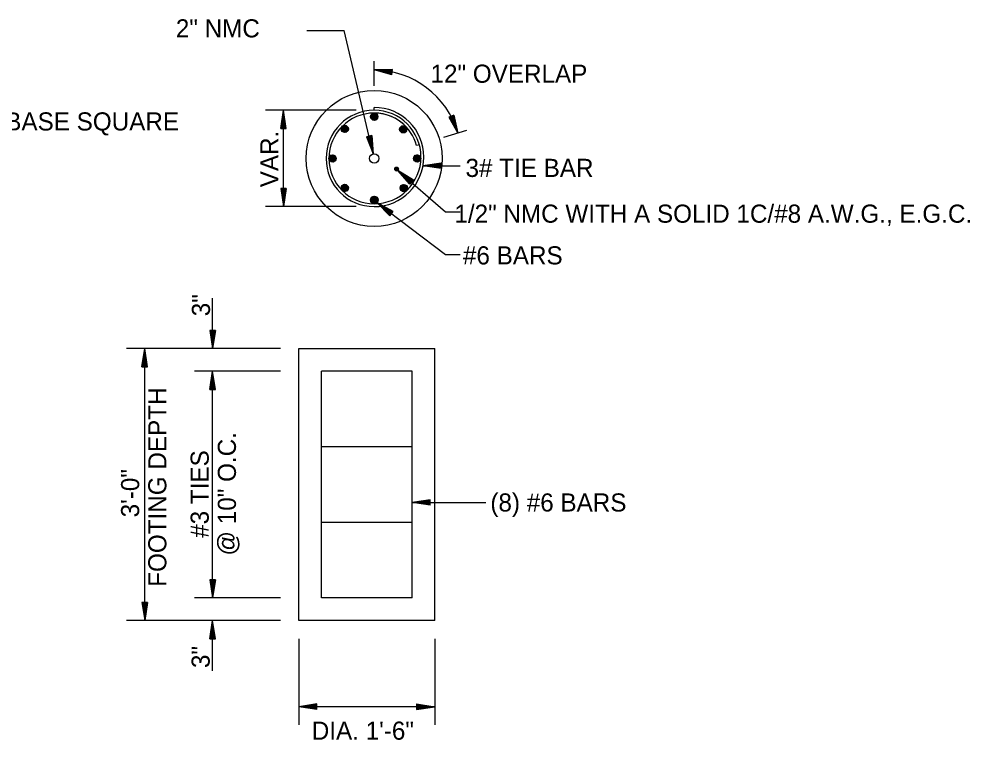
# Model space of a CAD drawing. Extents: x 418532 to 420296, y -565948 to -565286.
# Drawn here: x 419394.2 to 419630.3, y -565491.4 to -565312.5 of the extents above; entities that cross this region are included whole.
import ezdxf

# ---------------------------------------------------------------- set-up
doc = ezdxf.new("R2010")
doc.units = 0
doc.layers.add('R_Draft', color=7, linetype='Continuous')

msp = doc.modelspace()

# ---------------------------------------------------------------- linework, layer by layer
at = {"layer": 'R_Draft'}
for p, q in [((419465.68, -565315.3), (419474.89, -565315.3)), ((419482.12, -565345.92), (419474.89, -565315.3)), ((419482.39, -565329.06), (419482.39, -565322.9)), ((419486.94, -565324.96), (419482.39, -565325.05)), ((419486.77, -565326.29), (419482.39, -565325.05)), ((419486.93, -565325.07), (419483.14, -565325.15)), ((419486.78, -565326.18), (419483.14, -565325.15)), ((419486.91, -565325.18), (419483.9, -565325.25)), ((419486.8, -565326.07), (419483.9, -565325.25)), ((419486.9, -565325.29), (419484.65, -565325.34)), ((419486.81, -565325.96), (419484.65, -565325.34)), ((419486.88, -565325.41), (419485.4, -565325.44)), ((419486.83, -565325.84), (419485.4, -565325.44)), ((419486.87, -565325.52), (419486.15, -565325.53)), ((419486.84, -565325.73), (419486.15, -565325.53)), ((419486.77, -565326.29), (419486.94, -565324.96)), ((419477.89, -565335.1), (419455.39, -565335.1)), ((419459.21, -565339.6), (419459.89, -565335.1)), ((419459.32, -565339.6), (419459.89, -565335.86)), ((419459.89, -565359.01), (419459.89, -565335.1)), ((419460.56, -565339.6), (419459.89, -565335.1)), ((419460.45, -565339.6), (419459.89, -565335.86)), ((419481.49, -565336.75), (419482.43, -565335.81)), ((419481.49, -565336.58), (419482.26, -565335.82)), ((419481.5, -565336.89), (419482.57, -565335.83)), ((419481.54, -565337.01), (419482.69, -565335.86)), ((419482.39, -565335.1), (419482.39, -565334.4)), ((419459.44, -565339.6), (419459.89, -565336.63)), ((419459.55, -565339.6), (419459.89, -565337.38)), ((419459.67, -565339.6), (419459.89, -565338.14)), ((419460.33, -565339.6), (419459.89, -565336.63)), ((419460.22, -565339.6), (419459.89, -565337.38)), ((419460.11, -565339.6), (419459.89, -565338.14)), ((419481.55, -565336.36), (419482.04, -565335.88)), ((419481.59, -565337.13), (419482.8, -565335.91)), ((419481.65, -565337.22), (419482.9, -565335.97)), ((419481.72, -565337.31), (419482.99, -565336.04)), ((419481.8, -565337.39), (419483.07, -565336.12)), ((419481.89, -565337.46), (419483.14, -565336.21)), ((419481.99, -565337.52), (419483.19, -565336.31)), ((419482.1, -565337.56), (419483.24, -565336.43)), ((419482.23, -565337.6), (419483.27, -565336.55)), ((419482.38, -565337.61), (419483.29, -565336.7)), ((419482.55, -565337.59), (419483.27, -565336.87)), ((419482.79, -565337.51), (419483.19, -565337.12)), ((419502.14, -565336.36), (419500.88, -565336.84)), ((419500.88, -565336.84), (419503.12, -565340.8)), ((419500.98, -565336.8), (419502.85, -565340.1)), ((419501.09, -565336.76), (419502.57, -565339.38)), ((419501.2, -565336.72), (419502.31, -565338.68)), ((419501.3, -565336.68), (419502.03, -565337.97)), ((419501.41, -565336.64), (419501.76, -565337.26)), ((419501.61, -565336.56), (419501.76, -565337.26)), ((419501.71, -565336.52), (419502.03, -565337.97)), ((419501.82, -565336.48), (419502.31, -565338.68)), ((419501.93, -565336.44), (419502.57, -565339.38)), ((419502.03, -565336.4), (419502.85, -565340.1)), ((419502.14, -565336.36), (419503.12, -565340.8)), ((419459.21, -565339.6), (419460.56, -565339.6)), ((419459.78, -565339.6), (419459.89, -565338.89)), ((419459.99, -565339.6), (419459.89, -565338.89)), ((419474.17, -565339.7), (419475.03, -565338.84)), ((419474.17, -565339.85), (419475.18, -565338.85)), ((419474.2, -565339.99), (419475.31, -565338.87)), ((419474.2, -565339.51), (419474.84, -565338.87)), ((419474.24, -565340.1), (419475.43, -565338.92)), ((419474.3, -565340.21), (419475.53, -565338.97)), ((419474.34, -565339.21), (419474.54, -565339.01)), ((419474.36, -565340.3), (419475.63, -565339.04)), ((419474.44, -565340.38), (419475.71, -565339.11)), ((419474.52, -565340.46), (419475.79, -565339.2)), ((419474.62, -565340.52), (419475.85, -565339.29)), ((419474.73, -565340.57), (419475.9, -565339.4)), ((419474.85, -565340.61), (419475.94, -565339.52)), ((419474.98, -565340.64), (419475.96, -565339.66)), ((419475.14, -565340.64), (419475.96, -565339.81)), ((419475.34, -565340.6), (419475.92, -565340.01)), ((419488.71, -565339.92), (419489.68, -565338.95)), ((419488.71, -565339.77), (419489.53, -565338.95)), ((419488.73, -565340.06), (419489.82, -565338.97)), ((419488.75, -565339.57), (419489.33, -565338.99)), ((419488.77, -565340.18), (419489.94, -565339.01)), ((419488.82, -565340.29), (419490.05, -565339.06)), ((419488.88, -565340.38), (419490.14, -565339.12)), ((419488.96, -565340.47), (419490.23, -565339.2)), ((419489.04, -565340.54), (419490.31, -565339.28)), ((419489.13, -565340.61), (419490.37, -565339.37)), ((419489.24, -565340.66), (419490.43, -565339.48)), ((419489.36, -565340.71), (419490.47, -565339.59)), ((419489.49, -565340.73), (419490.5, -565339.73)), ((419489.64, -565340.74), (419490.5, -565339.88)), ((419489.83, -565340.71), (419490.47, -565340.06)), ((419490.12, -565340.58), (419490.34, -565340.36)), ((419505.27, -565340.15), (419499.62, -565341.86)), ((419481.77, -565341.38), (419480.45, -565341.68)), ((419480.45, -565341.68), (419482.12, -565345.92)), ((419480.56, -565341.66), (419481.95, -565345.19)), ((419480.68, -565341.63), (419481.78, -565344.43)), ((419480.79, -565341.61), (419481.61, -565343.7)), ((419480.9, -565341.58), (419481.44, -565342.96)), ((419481.01, -565341.56), (419481.27, -565342.22)), ((419481.22, -565341.51), (419481.27, -565342.22)), ((419481.33, -565341.48), (419481.44, -565342.96)), ((419481.44, -565341.46), (419481.61, -565343.7)), ((419481.55, -565341.43), (419481.78, -565344.43)), ((419481.66, -565341.41), (419481.95, -565345.19)), ((419481.77, -565341.38), (419482.12, -565345.92)), ((419493.59, -565343.68), (419492.91, -565343.88)), ((419471.14, -565347.01), (419471.99, -565346.16)), ((419471.14, -565347.17), (419472.15, -565346.17)), ((419471.17, -565347.3), (419472.28, -565346.19)), ((419471.17, -565346.83), (419471.8, -565346.19)), ((419471.21, -565347.42), (419472.4, -565346.23)), ((419471.26, -565347.52), (419472.5, -565346.29)), ((419471.32, -565346.51), (419471.49, -565346.34)), ((419471.33, -565347.62), (419472.59, -565346.35)), ((419471.41, -565347.7), (419472.68, -565346.43)), ((419471.49, -565347.77), (419472.75, -565346.51)), ((419471.59, -565347.84), (419472.82, -565346.61)), ((419471.69, -565347.89), (419472.87, -565346.72)), ((419471.81, -565347.93), (419472.91, -565346.83)), ((419471.95, -565347.95), (419472.93, -565346.97)), ((419472.1, -565347.96), (419472.93, -565347.13)), ((419472.3, -565347.92), (419472.9, -565347.32)), ((419492.15, -565347.05), (419493.03, -565346.16)), ((419492.16, -565347.2), (419493.18, -565346.17)), ((419492.17, -565346.87), (419492.85, -565346.18)), ((419492.19, -565347.33), (419493.31, -565346.2)), ((419492.23, -565347.44), (419493.43, -565346.24)), ((419492.27, -565346.61), (419492.59, -565346.28)), ((419492.29, -565347.54), (419493.53, -565346.3)), ((419492.35, -565347.63), (419493.62, -565346.37)), ((419492.43, -565347.72), (419493.7, -565346.44)), ((419492.52, -565347.79), (419493.77, -565346.53)), ((419492.62, -565347.85), (419493.84, -565346.63)), ((419492.72, -565347.9), (419493.89, -565346.74)), ((419492.85, -565347.94), (419493.92, -565346.86)), ((419492.99, -565347.96), (419493.94, -565347)), ((419493.15, -565347.95), (419493.94, -565347.16)), ((419493.36, -565347.9), (419493.89, -565347.37)), ((419487.46, -565349.68), (419487.93, -565349.22)), ((419487.48, -565349.82), (419488.07, -565349.23)), ((419487.51, -565349.47), (419487.71, -565349.27)), ((419487.53, -565349.93), (419488.18, -565349.28)), ((419487.6, -565350.02), (419488.26, -565349.35)), ((419487.69, -565350.09), (419488.33, -565349.44)), ((419487.8, -565350.13), (419488.38, -565349.56)), ((419487.94, -565350.15), (419488.4, -565349.7)), ((419488.17, -565350.09), (419488.34, -565349.92)), ((419488.26, -565350.02), (419500.1, -565360.35)), ((419491.23, -565353.48), (419488.26, -565350.02)), ((419492.11, -565352.45), (419488.26, -565350.02)), ((419498.99, -565348.23), (419494.49, -565348.91)), ((419494.49, -565348.91), (419503.7, -565348.91)), ((419498.99, -565349.58), (419494.49, -565348.91)), ((419498.99, -565348.35), (419495.25, -565348.91)), ((419498.99, -565349.47), (419495.25, -565348.91)), ((419498.99, -565348.46), (419496.02, -565348.91)), ((419498.99, -565349.36), (419496.02, -565348.91)), ((419498.99, -565348.57), (419496.77, -565348.91)), ((419498.99, -565349.24), (419496.77, -565348.91)), ((419498.99, -565348.69), (419497.53, -565348.91)), ((419498.99, -565349.13), (419497.53, -565348.91)), ((419498.99, -565348.8), (419498.28, -565348.91)), ((419498.99, -565349.01), (419498.28, -565348.91)), ((419498.99, -565349.58), (419498.99, -565348.23)), ((419491.3, -565353.39), (419488.83, -565350.52)), ((419492.04, -565352.54), (419488.83, -565350.52)), ((419491.96, -565352.63), (419489.42, -565351.02)), ((419491.38, -565353.3), (419489.42, -565351.02)), ((419491.45, -565353.22), (419489.98, -565351.51)), ((419491.89, -565352.71), (419489.98, -565351.51)), ((419491.81, -565352.8), (419490.56, -565352.01)), ((419491.53, -565353.13), (419490.56, -565352.01)), ((419459.21, -565354.51), (419459.89, -565359.01)), ((419460.56, -565354.51), (419459.21, -565354.51)), ((419459.32, -565354.51), (419459.89, -565358.26)), ((419459.44, -565354.51), (419459.89, -565357.49)), ((419459.55, -565354.51), (419459.89, -565356.74)), ((419459.67, -565354.51), (419459.89, -565355.98)), ((419459.78, -565354.51), (419459.89, -565355.22)), ((419460.56, -565354.51), (419459.89, -565359.01)), ((419460.1, -565354.51), (419459.89, -565355.98)), ((419460.33, -565354.51), (419459.89, -565357.49)), ((419460.45, -565354.51), (419459.89, -565358.26)), ((419460.22, -565354.51), (419459.89, -565356.74)), ((419459.99, -565354.51), (419459.89, -565355.22)), ((419474.17, -565354.46), (419475.15, -565353.48)), ((419474.17, -565354.3), (419474.99, -565353.48)), ((419474.19, -565354.6), (419475.29, -565353.5)), ((419474.21, -565354.1), (419474.79, -565353.52)), ((419474.23, -565354.72), (419475.41, -565353.54)), ((419474.29, -565354.82), (419475.51, -565353.6)), ((419474.35, -565354.92), (419475.61, -565353.66)), ((419474.42, -565355.01), (419475.69, -565353.73)), ((419474.51, -565355.08), (419475.77, -565353.82)), ((419474.6, -565355.15), (419475.84, -565353.91)), ((419474.7, -565355.2), (419475.89, -565354.01)), ((419474.82, -565355.24), (419475.93, -565354.13)), ((419474.95, -565355.27), (419475.96, -565354.26)), ((419475.11, -565355.28), (419475.97, -565354.42)), ((419475.29, -565355.25), (419475.94, -565354.6)), ((419488.85, -565354.38), (419489.71, -565353.52)), ((419488.86, -565354.53), (419489.86, -565353.53)), ((419488.88, -565354.19), (419489.52, -565353.55)), ((419488.88, -565354.66), (419489.99, -565353.56)), ((419488.92, -565354.78), (419490.11, -565353.6)), ((419488.98, -565354.89), (419490.21, -565353.65)), ((419489.03, -565353.88), (419489.21, -565353.7)), ((419489.04, -565354.98), (419490.31, -565353.72)), ((419489.12, -565355.06), (419490.39, -565353.79)), ((419489.2, -565355.14), (419490.47, -565353.88)), ((419489.3, -565355.2), (419490.53, -565353.97)), ((419489.41, -565355.25), (419490.58, -565354.08)), ((419489.53, -565355.29), (419490.62, -565354.2)), ((419489.66, -565355.32), (419490.64, -565354.33)), ((419489.82, -565355.32), (419490.65, -565354.49)), ((419490.02, -565355.28), (419490.61, -565354.69)), ((419491.74, -565352.89), (419491.13, -565352.5)), ((419491.6, -565353.05), (419491.13, -565352.5)), ((419491.23, -565353.48), (419492.11, -565352.45)), ((419475.59, -565355.11), (419475.8, -565354.9)), ((419481.45, -565357.46), (419482.47, -565356.44)), ((419481.45, -565357.3), (419482.31, -565356.44)), ((419481.48, -565357.59), (419482.61, -565356.46)), ((419481.49, -565357.1), (419482.12, -565356.47)), ((419481.51, -565357.71), (419482.73, -565356.5)), ((419481.56, -565357.82), (419482.84, -565356.55)), ((419481.63, -565357.92), (419482.93, -565356.61)), ((419481.69, -565356.74), (419481.75, -565356.68)), ((419481.7, -565358.01), (419483.02, -565356.68)), ((419481.78, -565358.09), (419483.1, -565356.76)), ((419481.87, -565358.15), (419483.17, -565356.86)), ((419481.97, -565358.21), (419483.23, -565356.96)), ((419482.08, -565358.26), (419483.27, -565357.07)), ((419477.89, -565359.01), (419455.39, -565359.01)), ((419482.21, -565358.29), (419483.31, -565357.19)), ((419482.35, -565358.31), (419483.32, -565357.34)), ((419482.52, -565358.3), (419483.31, -565357.51)), ((419482.74, -565358.24), (419483.25, -565357.72)), ((419483.06, -565358.03), (419500.1, -565370.91)), ((419486.25, -565361.27), (419483.06, -565358.03)), ((419487.06, -565360.2), (419483.06, -565358.03)), ((419486.31, -565361.18), (419483.66, -565358.48)), ((419486.99, -565360.29), (419483.66, -565358.48)), ((419486.92, -565360.38), (419484.28, -565358.95)), ((419486.38, -565361.09), (419484.28, -565358.95)), ((419486.45, -565361), (419484.88, -565359.4)), ((419486.85, -565360.47), (419484.88, -565359.4)), ((419486.79, -565360.56), (419485.48, -565359.86)), ((419486.52, -565360.91), (419485.48, -565359.86)), ((419486.72, -565360.65), (419486.08, -565360.31)), ((419486.59, -565360.82), (419486.08, -565360.31)), ((419486.25, -565361.27), (419487.06, -565360.2)), ((419500.1, -565360.35), (419503.7, -565360.35)), ((419500.1, -565370.91), (419503.7, -565370.91)), ((419442.28, -565394.26), (419442.28, -565381.75)), ((419441.61, -565389.76), (419442.28, -565394.26)), ((419442.96, -565389.76), (419441.61, -565389.76)), ((419441.72, -565389.76), (419442.28, -565393.51)), ((419441.84, -565389.76), (419442.28, -565392.73)), ((419441.95, -565389.76), (419442.28, -565391.99)), ((419442.06, -565389.76), (419442.28, -565391.22)), ((419442.18, -565389.76), (419442.28, -565390.47)), ((419442.96, -565389.76), (419442.28, -565394.26)), ((419442.5, -565389.76), (419442.28, -565391.22)), ((419442.73, -565389.76), (419442.28, -565392.73)), ((419442.85, -565389.76), (419442.28, -565393.51)), ((419442.62, -565389.76), (419442.28, -565391.99)), ((419442.39, -565389.76), (419442.28, -565390.47)), ((419459.16, -565394.26), (419420.91, -565394.26)), ((419424.73, -565398.76), (419425.41, -565394.26)), ((419425.41, -565461.76), (419425.41, -565394.26)), ((419426.08, -565398.76), (419425.41, -565394.26)), ((419463.66, -565461.76), (419463.66, -565394.26)), ((419463.66, -565394.26), (419497.41, -565394.26)), ((419497.41, -565461.76), (419497.41, -565394.26)), ((419424.85, -565398.76), (419425.41, -565395.01)), ((419424.96, -565398.76), (419425.41, -565395.79)), ((419425.07, -565398.76), (419425.41, -565396.53)), ((419425.97, -565398.76), (419425.41, -565395.01)), ((419425.86, -565398.76), (419425.41, -565395.79)), ((419425.74, -565398.76), (419425.41, -565396.53)), ((419424.73, -565398.76), (419426.08, -565398.76)), ((419425.19, -565398.76), (419425.41, -565397.3)), ((419425.3, -565398.76), (419425.41, -565398.05)), ((419425.63, -565398.76), (419425.41, -565397.3)), ((419425.52, -565398.76), (419425.41, -565398.05)), ((419459.16, -565399.88), (419437.78, -565399.88)), ((419441.61, -565404.38), (419442.28, -565399.88)), ((419441.72, -565404.38), (419442.28, -565400.64)), ((419441.84, -565404.38), (419442.28, -565401.41)), ((419442.28, -565456.13), (419442.28, -565399.88)), ((419442.96, -565404.38), (419442.28, -565399.88)), ((419442.85, -565404.38), (419442.28, -565400.64)), ((419442.73, -565404.38), (419442.28, -565401.41)), ((419491.78, -565399.88), (419469.28, -565399.88)), ((419469.28, -565456.13), (419469.28, -565399.88)), ((419491.78, -565456.13), (419491.78, -565399.88)), ((419441.95, -565404.38), (419442.28, -565402.16)), ((419442.07, -565404.38), (419442.28, -565402.92)), ((419442.18, -565404.38), (419442.28, -565403.67)), ((419442.62, -565404.38), (419442.28, -565402.16)), ((419442.5, -565404.38), (419442.28, -565402.92)), ((419442.39, -565404.38), (419442.28, -565403.67)), ((419441.61, -565404.38), (419442.96, -565404.38)), ((419491.78, -565418.63), (419469.28, -565418.63)), ((419496.29, -565431.78), (419491.79, -565432.45)), ((419496.29, -565433.13), (419491.79, -565432.45)), ((419491.79, -565432.45), (419510.12, -565432.45)), ((419496.29, -565431.89), (419492.55, -565432.45)), ((419496.29, -565433.01), (419492.55, -565432.45)), ((419496.29, -565432), (419493.32, -565432.45)), ((419496.29, -565432.9), (419493.32, -565432.45)), ((419496.29, -565432.12), (419494.07, -565432.45)), ((419496.29, -565432.79), (419494.07, -565432.45)), ((419496.29, -565432.23), (419494.83, -565432.45)), ((419496.29, -565432.67), (419494.83, -565432.45)), ((419496.29, -565432.35), (419495.58, -565432.45)), ((419496.29, -565432.56), (419495.58, -565432.45)), ((419496.29, -565433.13), (419496.29, -565431.78)), ((419491.78, -565437.38), (419469.28, -565437.38)), ((419441.61, -565451.63), (419442.28, -565456.13)), ((419442.96, -565451.63), (419441.61, -565451.63)), ((419441.72, -565451.63), (419442.28, -565455.38)), ((419441.84, -565451.63), (419442.28, -565454.61)), ((419441.95, -565451.63), (419442.28, -565453.86)), ((419442.06, -565451.63), (419442.28, -565453.1)), ((419442.18, -565451.63), (419442.28, -565452.35)), ((419442.96, -565451.63), (419442.28, -565456.13)), ((419442.5, -565451.63), (419442.28, -565453.1)), ((419442.73, -565451.63), (419442.28, -565454.61)), ((419442.85, -565451.63), (419442.28, -565455.38)), ((419442.62, -565451.63), (419442.28, -565453.86)), ((419442.39, -565451.63), (419442.28, -565452.35)), ((419459.16, -565456.13), (419437.78, -565456.13)), ((419491.78, -565456.13), (419469.28, -565456.13)), ((419424.73, -565457.26), (419425.41, -565461.76)), ((419426.08, -565457.26), (419424.73, -565457.26)), ((419424.85, -565457.26), (419425.41, -565461.01)), ((419424.96, -565457.26), (419425.41, -565460.23)), ((419425.07, -565457.26), (419425.41, -565459.49)), ((419425.19, -565457.26), (419425.41, -565458.72)), ((419425.3, -565457.26), (419425.41, -565457.97)), ((419426.08, -565457.26), (419425.41, -565461.76)), ((419425.63, -565457.26), (419425.41, -565458.72)), ((419425.86, -565457.26), (419425.41, -565460.23)), ((419425.97, -565457.26), (419425.41, -565461.01)), ((419425.74, -565457.26), (419425.41, -565459.49)), ((419425.52, -565457.26), (419425.41, -565457.97)), ((419459.16, -565461.76), (419420.91, -565461.76)), ((419441.61, -565466.26), (419442.28, -565461.76)), ((419441.72, -565466.26), (419442.28, -565462.51)), ((419441.84, -565466.26), (419442.28, -565463.29)), ((419442.28, -565474.27), (419442.28, -565461.76)), ((419442.96, -565466.26), (419442.28, -565461.76)), ((419442.85, -565466.26), (419442.28, -565462.51)), ((419442.73, -565466.26), (419442.28, -565463.29)), ((419497.41, -565461.76), (419463.66, -565461.76)), ((419441.95, -565466.26), (419442.28, -565464.03)), ((419442.07, -565466.26), (419442.28, -565464.8)), ((419442.18, -565466.26), (419442.28, -565465.55)), ((419442.62, -565466.26), (419442.28, -565464.03)), ((419442.5, -565466.26), (419442.28, -565464.8)), ((419442.39, -565466.26), (419442.28, -565465.55)), ((419441.61, -565466.26), (419442.96, -565466.26)), ((419463.66, -565466.26), (419463.66, -565487.63)), ((419497.41, -565466.26), (419497.41, -565487.63)), ((419468.16, -565482.46), (419463.66, -565483.13)), ((419497.41, -565483.13), (419463.66, -565483.13)), ((419468.16, -565483.81), (419463.66, -565483.13)), ((419468.16, -565482.57), (419464.41, -565483.13)), ((419468.16, -565483.7), (419464.41, -565483.13)), ((419468.16, -565482.69), (419465.18, -565483.13)), ((419468.16, -565483.58), (419465.18, -565483.13)), ((419468.16, -565482.8), (419465.93, -565483.13)), ((419468.16, -565483.47), (419465.93, -565483.13)), ((419468.16, -565482.91), (419466.7, -565483.13)), ((419468.16, -565483.35), (419466.7, -565483.13)), ((419468.16, -565483.03), (419467.45, -565483.13)), ((419468.16, -565483.24), (419467.45, -565483.13)), ((419468.16, -565483.81), (419468.16, -565482.46)), ((419492.91, -565482.46), (419497.41, -565483.13)), ((419492.91, -565482.46), (419492.91, -565483.81)), ((419492.91, -565482.57), (419496.66, -565483.13)), ((419492.91, -565482.69), (419495.88, -565483.13)), ((419492.91, -565482.8), (419495.13, -565483.13)), ((419492.91, -565482.92), (419494.37, -565483.13)), ((419492.91, -565483.03), (419493.62, -565483.13)), ((419492.91, -565483.81), (419497.41, -565483.13)), ((419492.91, -565483.36), (419494.37, -565483.13)), ((419492.91, -565483.58), (419495.88, -565483.13)), ((419492.91, -565483.7), (419496.66, -565483.13)), ((419492.91, -565483.47), (419495.13, -565483.13)), ((419492.91, -565483.24), (419493.62, -565483.13))]:
    msp.add_line(p, q, dxfattribs=at)
for centre, radius in [((419482.39, -565347.06), 16.87), ((419482.39, -565336.71), 0.9), ((419475.07, -565339.74), 0.9), ((419489.6, -565339.84), 0.9), ((419472.04, -565347.06), 0.9), ((419482.39, -565347.06), 1.17), ((419493.05, -565347.06), 0.9), ((419487.93, -565349.68), 0.469), ((419475.07, -565354.38), 0.9), ((419489.75, -565354.42), 0.9), ((419482.39, -565357.37), 0.937)]:
    msp.add_circle(centre, radius, dxfattribs=at)
for centre, radius, start, end in [((419482.39, -565346.71), 21.56, 15.8939, 90), ((419482.39, -565347.06), 11.95, 90, 270), ((419482.39, -565347.06), 11.25, 90, 270), ((419482.39, -565346.71), 12.31, 270, 90), ((419482.39, -565346.71), 11.6, 270, 90), ((419482.39, -565346.71), 10.9, 43.6894, 90), ((419482.39, -565346.71), 10.9, 15.0162, 90)]:
    msp.add_arc(centre, radius, start, end, dxfattribs=at)

# ---------------------------------------------------------------- texts
for s, p in [('2" NMC', (419433.14, -565317.03)), ('12" OVERLAP', (419496.36, -565328.28)), ('ANCHOR BASE SQUARE', (419363.05, -565340.13)), ('3# TIE BAR', (419505.05, -565351.66)), (' 1/2" NMC WITH A SOLID 1C/#8 A.W.G., E.G.C.', (419500.62, -565363.02)), ('#6 BARS', (419504.41, -565373.37)), ('(8) #6 BARS', (419511.22, -565434.7)), ('DIA. 1\'-6"', (419466.89, -565491.33))]:
    msp.add_text(s, height=4.5, dxfattribs=at).set_placement(p)
for s, p in [('VAR.', (419458.61, -565354.22)), ('3"', (419441.62, -565386.23)), ('FOOTING DEPTH', (419430.79, -565453.38)), ('@ 10" O.C.', (419448.06, -565445.63)), ('#3 TIES', (419441.31, -565441.23)), ('3\'-0"', (419424.04, -565436.14)), ('3"', (419441.55, -565473.55))]:
    msp.add_text(s, height=4.5, rotation=90, dxfattribs=at).set_placement(p)

doc.saveas('drawing.dxf')
